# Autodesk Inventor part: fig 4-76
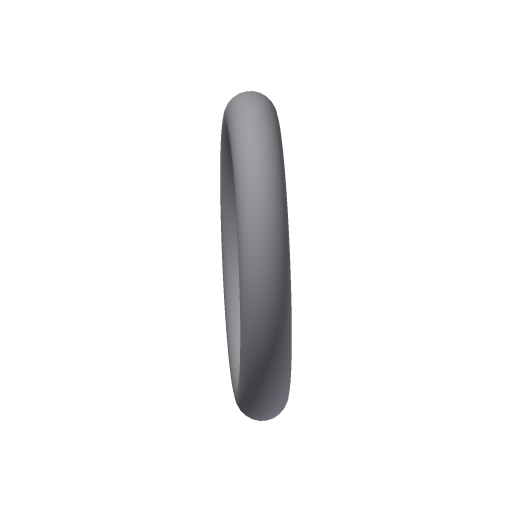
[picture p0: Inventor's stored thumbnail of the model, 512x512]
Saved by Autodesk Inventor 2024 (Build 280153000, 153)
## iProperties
Created: 2012-07
Part Number: fig 4-76
Material: Generic
Document SubType Name: Modeling
Designer: CADCIM
Density: 1 g/cm^3
Appearance: Default
Author: CADCIM
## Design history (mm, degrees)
sketch "Sketch1"
  geometry: L1 (-1.626, -1.876)-(1.626, 1.876); L2 (0, 0)-(7.504, -6.505); C1 r 1.845 at (7.504, -6.505)
  constraints: 4 end point, 1 centre point, 1 midpoint, 1 perpendicular
  dimensions: "d0" = 90 deg dimension on L2.end C1 L1.start L1.end L1 L2.start L2
revolve "Revolution1" sketch "Sketch1" stored, may be unused: angle "d0" = 90 deg
body "Solid1"
